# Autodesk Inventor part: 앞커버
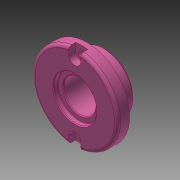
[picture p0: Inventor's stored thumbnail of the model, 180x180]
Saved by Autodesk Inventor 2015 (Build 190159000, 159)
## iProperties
Created: 2022-03
Part Number: 앞커버
Material: Generic
Document SubType Name: Modeling
Designer: mdu-01
Density: 1 g/cm^3
Appearance: 분홍색
Author: mdu-01
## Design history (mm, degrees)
sketch "스케치1"
  geometry: L1 (0, 0)-(0, -20); L2 (14, 0)-(28, 0); L3 (28, 0)-(28, -8); L4 (28, -8)-(19, -8); L5 (19, -8)-(19, -20); L6 (19, -20)-(10.5, -20); L7 (14, 0)-(14, -3); L8 (14, -3)-(10.5, -3); L9 (10.5, -3)-(10.5, -20)
  constraints: 18 end point, 5 perpendicular, 2 horizontal alignment, 2 parallel, 1 horizontal, 1 vertical
  dimensions: "d0" = 56 diameter of L3 L1; "d2" = 38 diameter of L5 L1; "d3" = 8 distance of L2.end L3.end; "d4" = 20 distance between parallel lines of L2 L6; "d5" = 21 diameter of L9 L1; "d6" = 28 diameter of L7 L1; "d7" = 3 distance of L2.start L7.end
revolve "회전1" sketch "스케치1" stored, may be unused: angle "d8" = 90 deg
fillet "모깎기1" dims "d9" = 0.5
chamfer "모따기1" distance "d10" = 0.5; stored, may be unused: second distance "d11" = 2, angle "d12" = 45 deg
chamfer "모따기2" distance "d13" = 1; stored, may be unused: second distance "d14" = 2, angle "d15" = 45 deg
fillet "모깎기2" dims "d32" = 2
sketch "스케치2" dims "d16" = 46
  geometry: 3 further points
  constraints: 2 vertical alignment, 1 coincident, 2 other
hole "구멍1" sketch "스케치2" at (0, 23) diameter "d18" = 4.5; stored, may be unused: countersink angle "d22" = 90 deg, drill point angle "d24" = 118 deg; dims "d19" = 6, "d20" = 8, "d21" = 4.6, "d23" = 8
sketch "스케치3"
  geometry: L1 (4, 23)-(4, 27.713); L2 (-4, 23)-(-4, 27.713); A1 r 4 centre (0, 23) between (-4, 23) and (4, 23) reference; A2 r 28 centre (0, 0) between (4, 27.713) and (-4, 27.713) reference; 1 further point
  constraints: 4 end point, 4 point on circle, 2 tangent, 1 parallel, 1 vertical
extrude "돌출1" cut sketch "스케치3" stored distance "d27" = 10; taper "d28" = 0 deg
fillet "모깎기3" dims "d33" = 0.3
node "솔리드1"
pattern_circular "원형 패턴1" dims angle "d30" = 360 deg
